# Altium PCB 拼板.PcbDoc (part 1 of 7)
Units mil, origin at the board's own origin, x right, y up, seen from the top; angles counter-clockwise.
Board outline 3630.03 x 5330.03 mil, 2 copper layers (Top Layer, Bottom Layer); 416 components, 35 nets, 1936 pads, 800 vias.
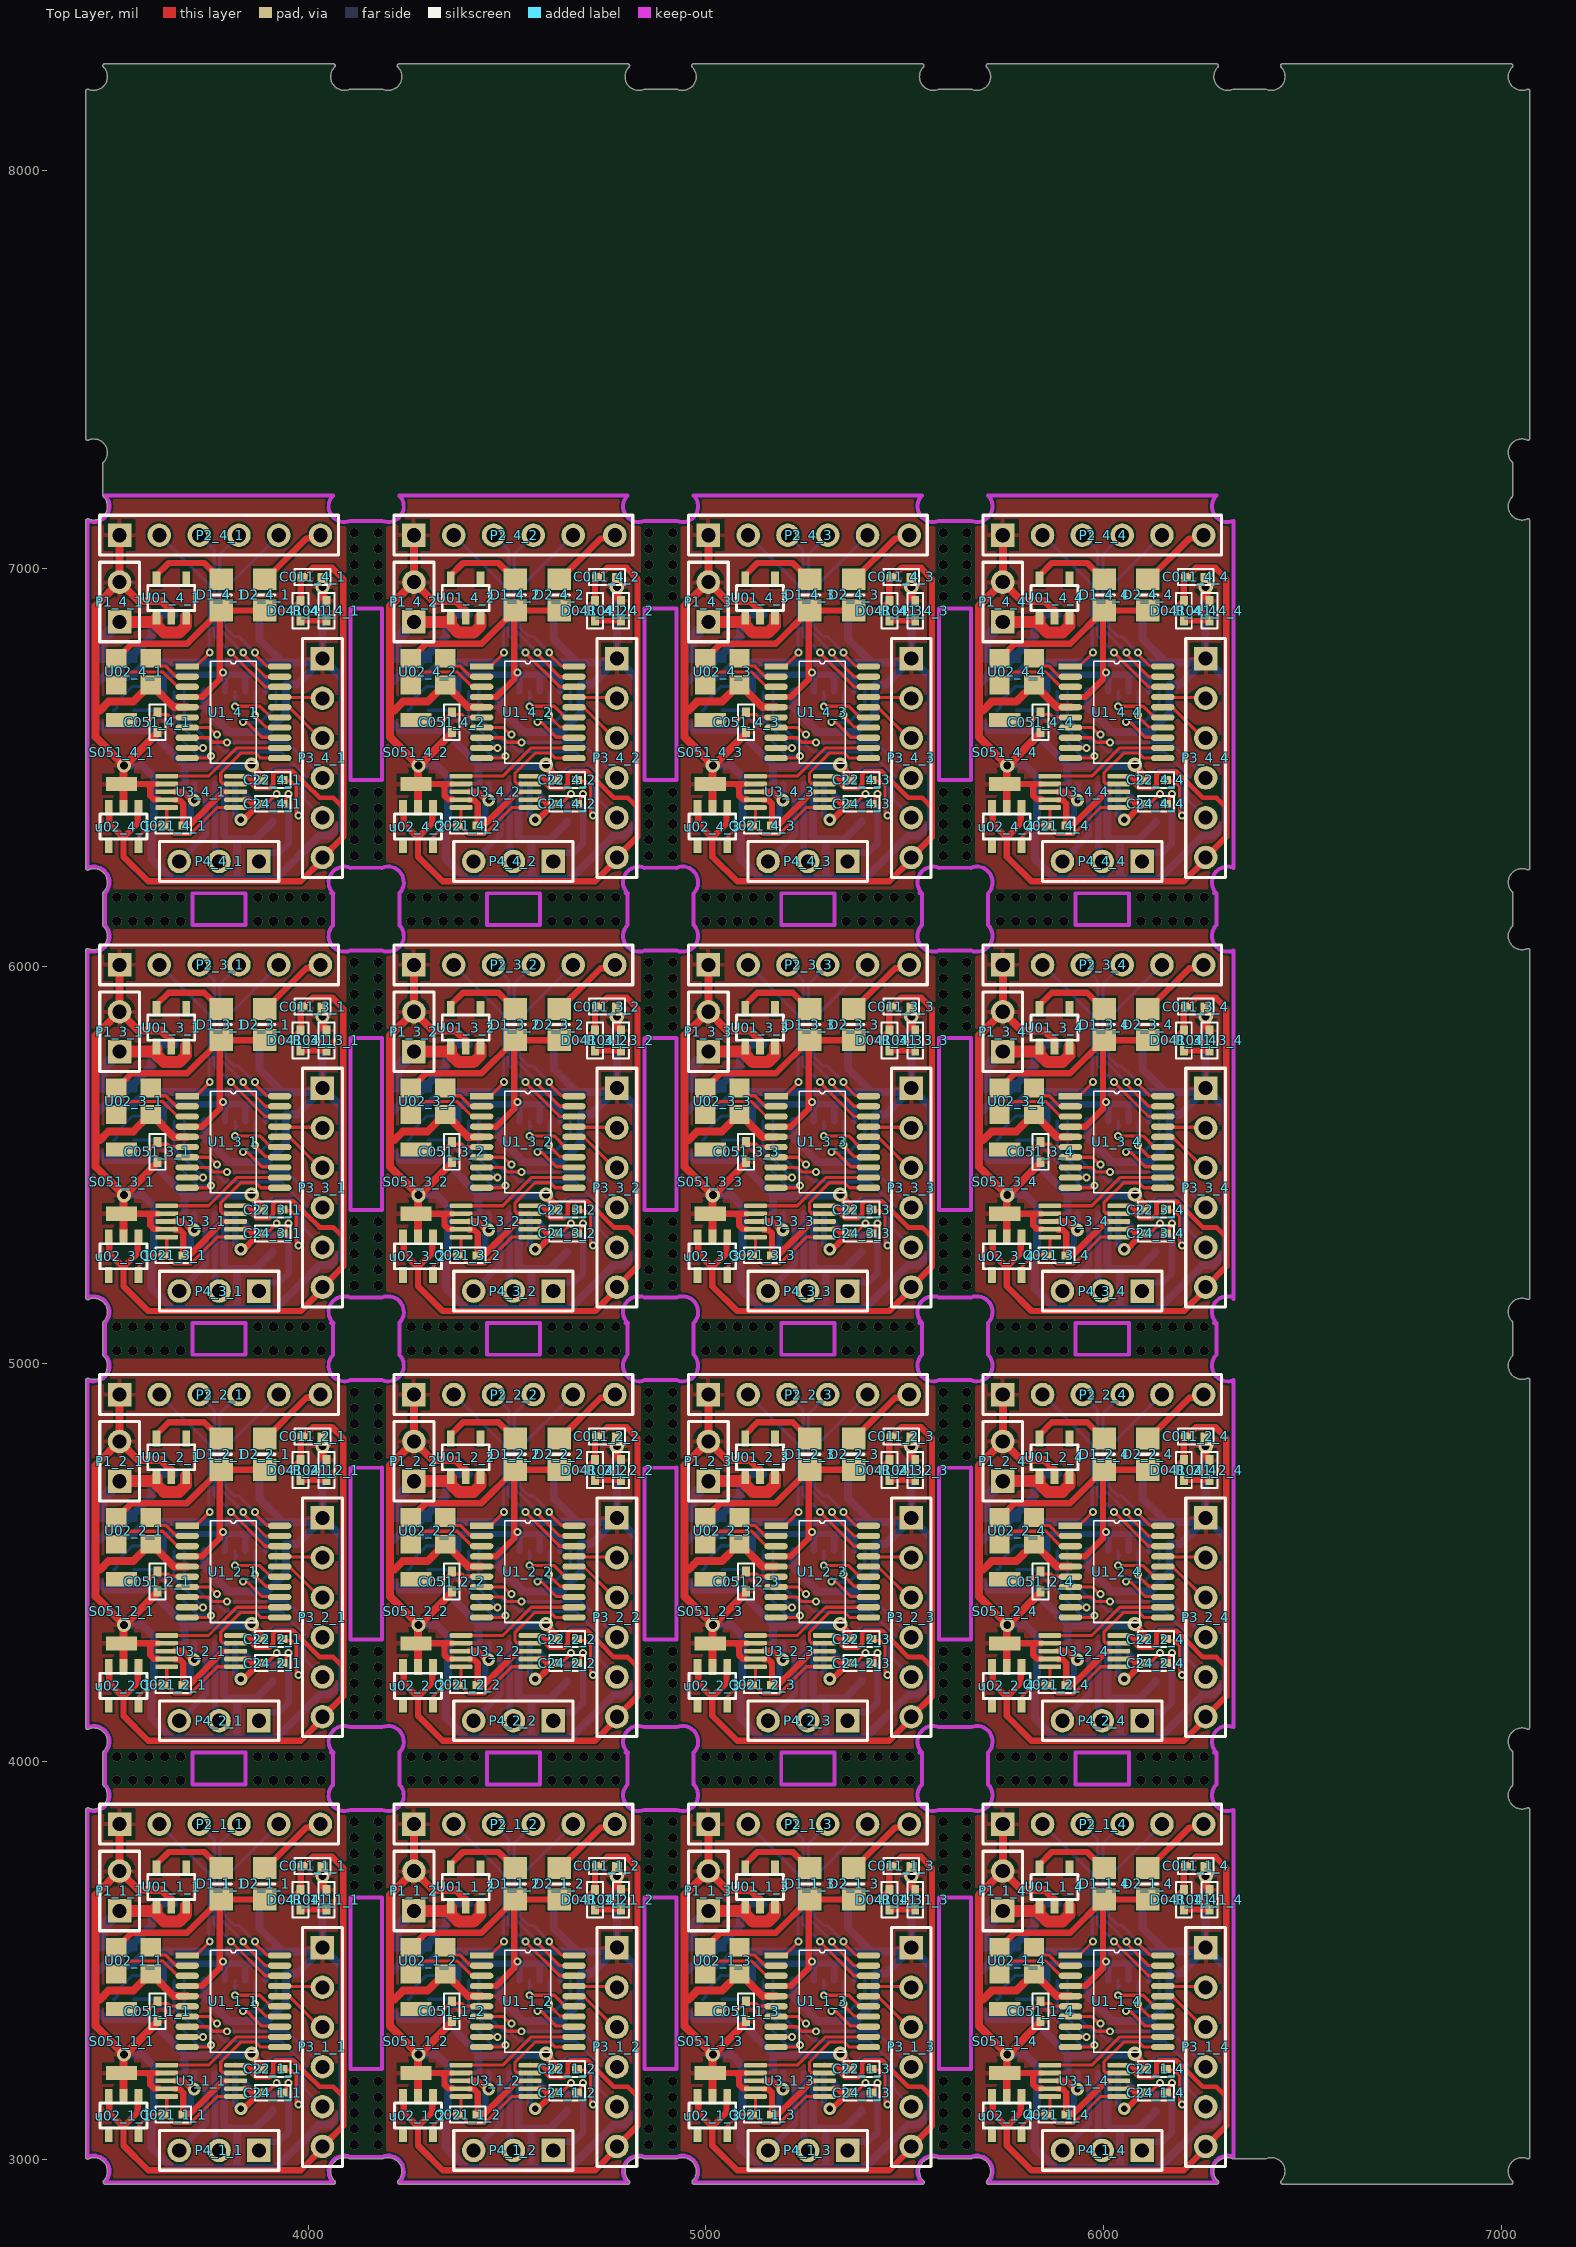
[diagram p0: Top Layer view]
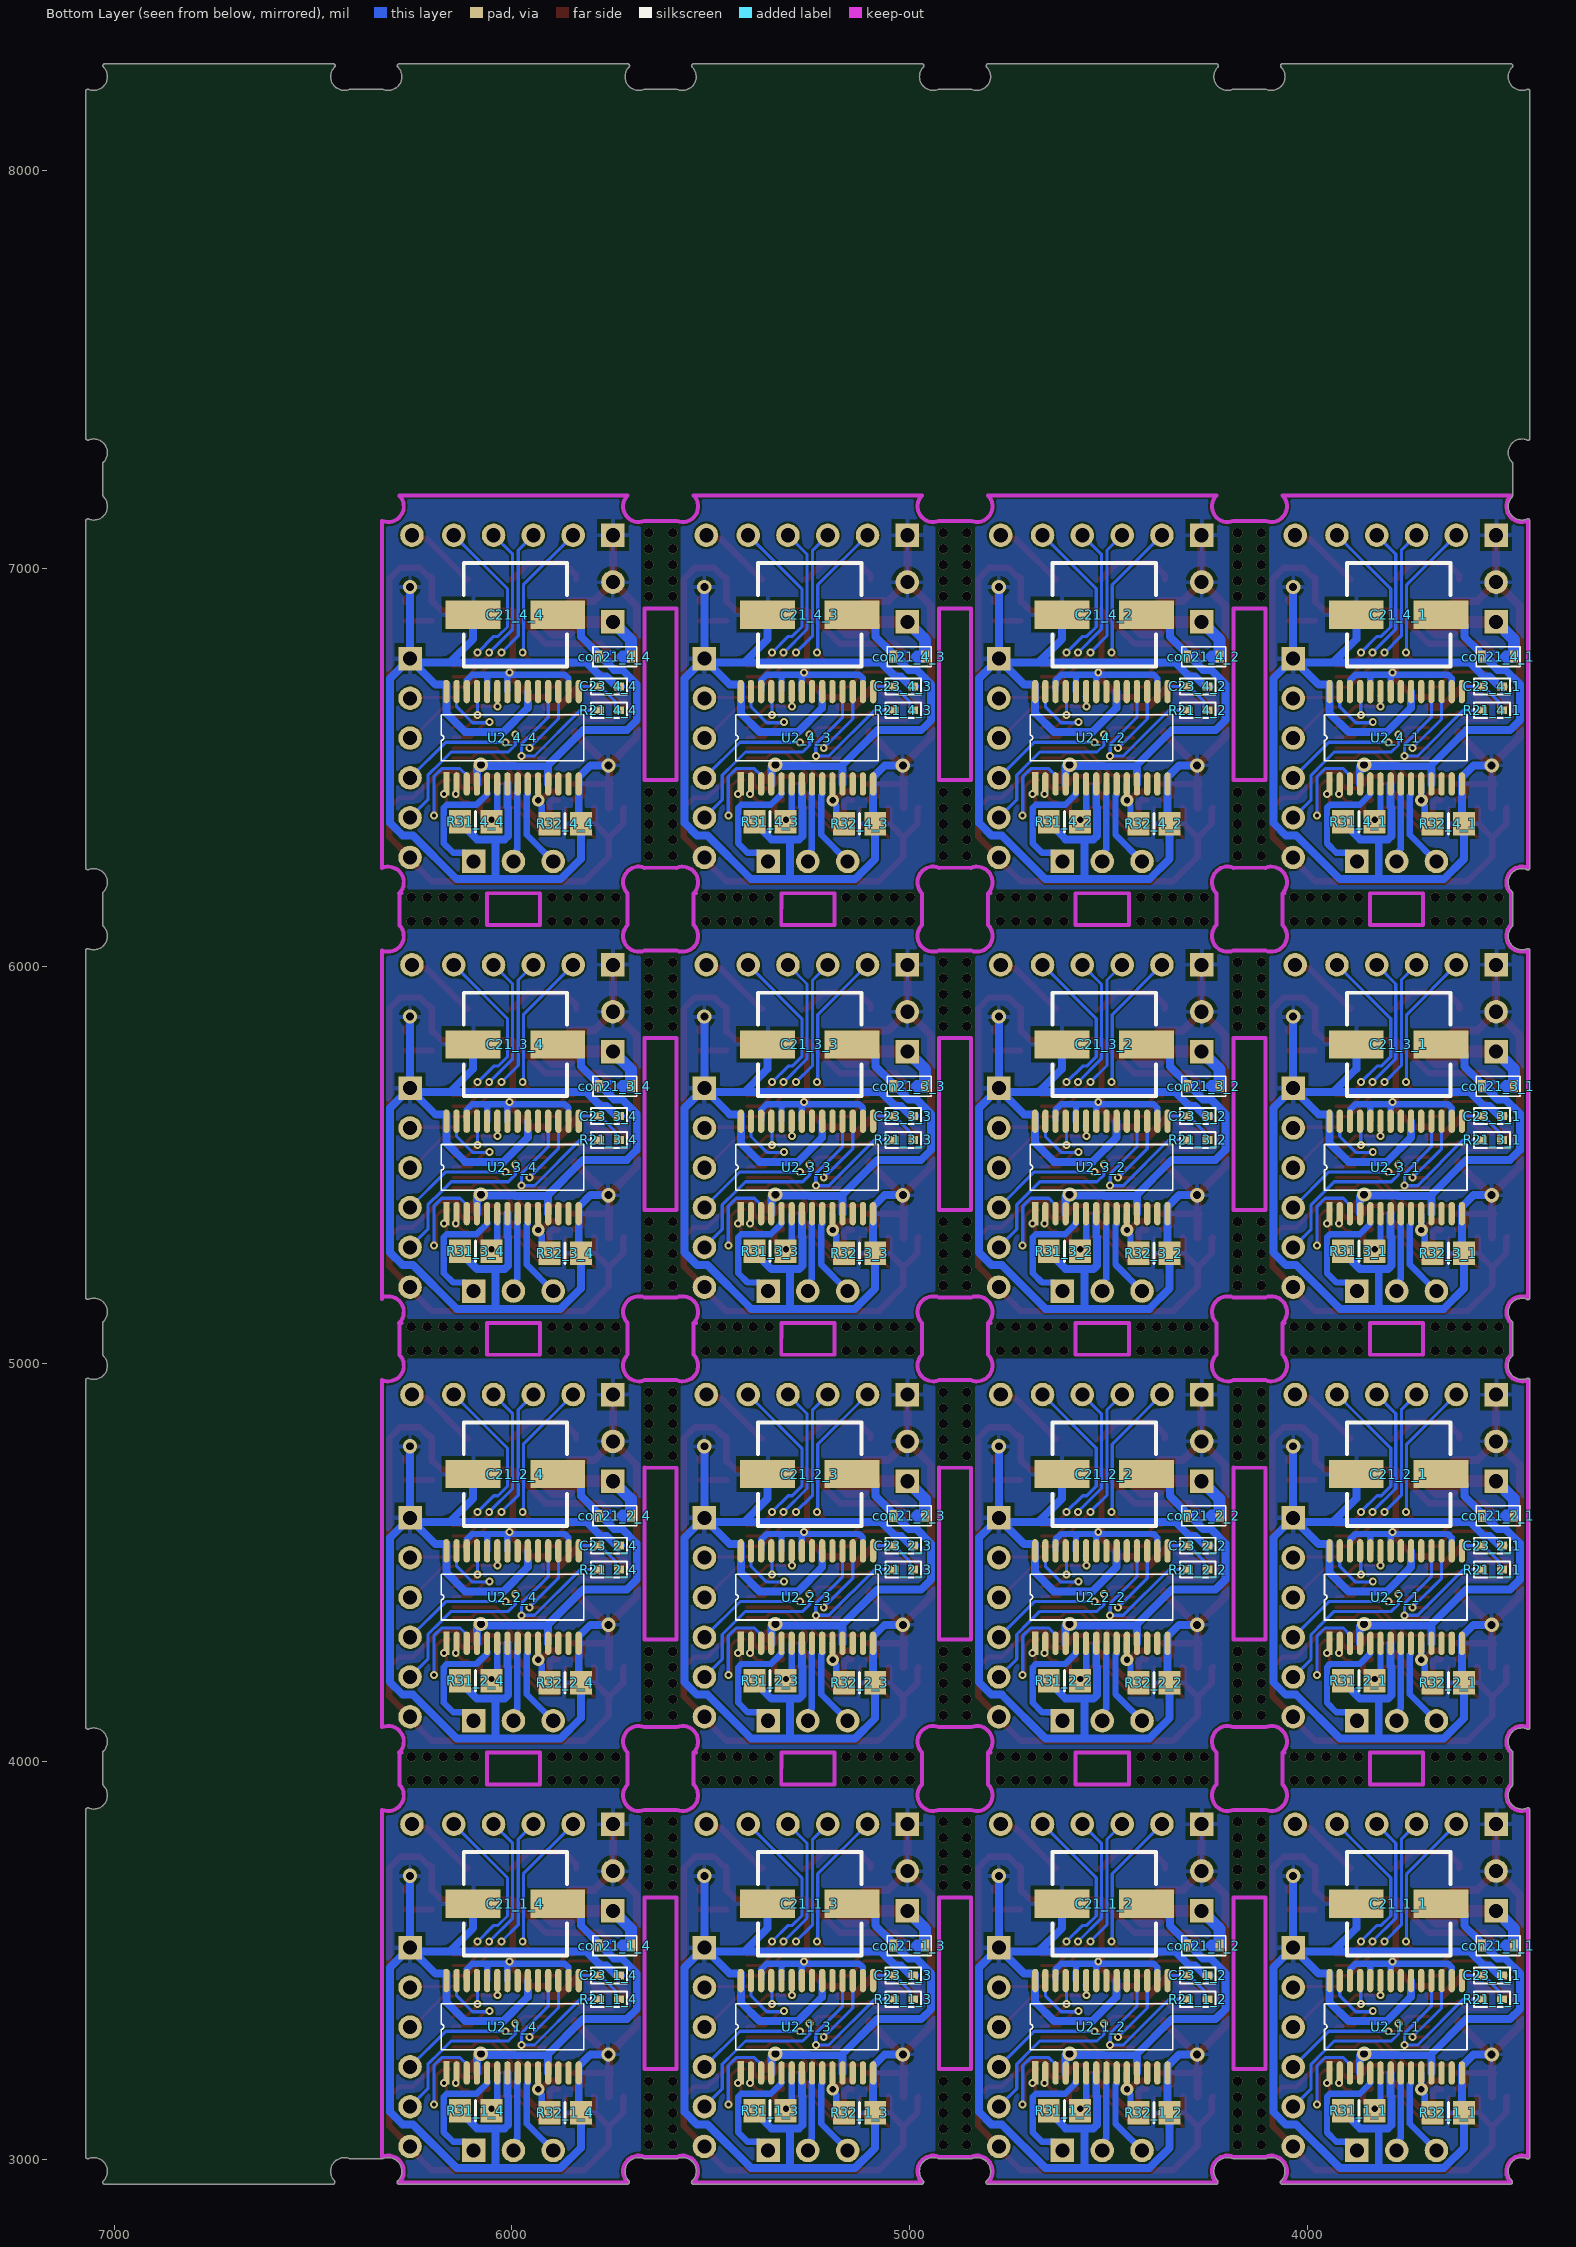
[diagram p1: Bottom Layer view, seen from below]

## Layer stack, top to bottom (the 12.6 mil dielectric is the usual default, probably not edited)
Top Solder: solder mask 0.4, Solder Resist, Dk 3.5
Top Layer: signal copper 1.4
Dielectric 1: dielectric 12.6, FR-4, Dk 4.8
Bottom Layer: signal copper 1.4
Bottom Solder: solder mask 0.4, Solder Resist, Dk 3.5

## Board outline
3441.05,3006.39 3441.05,3879.08 cw(c3446.07,3879.08) 3447.98,3883.71 ccw(c3461.11,3915.46) 3495.46,3915.46 ccw(c3461.11,3915.46) 3485.66,3939.49 ccw(c3461.11,3915.46) 3485.64,3939.51 cw(c3489.22,3943.02) 3484.21,3943.04 3484.21,3943.01 ccw(c3489.22,3943.02) 3485.66,3939.49 3484.21,3943.04 3484.05,4023.01 cw(c3489.07,4023.02) 3486.27,4027.19 cw(c3490.1,4023.95) 3486.41,4027.34 ccw(c3461.11,4050.58) 3495.46,4050.58 ccw(c3461.11,4050.58) 3449.77,4083.01 cw(c3446.07,4086.39) 3441.05,4086.39 3441.05,4959.08 cw(c3446.07,4959.08) 3447.98,4963.71 ccw(c3461.11,4995.46) 3495.46,4995.46 ccw(c3461.11,4995.46) 3485.66,5019.49 ccw(c3461.11,4995.46) 3485.64,5019.51 cw(c3489.22,5023.02) 3484.21,5023.04 3484.05,5103.01 cw(c3489.07,5103.02) 3486.27,5107.19 cw(c3490.1,5103.95) 3486.41,5107.34 ccw(c3461.11,5130.58) 3495.46,5130.58 ccw(c3461.11,5130.58) 3449.77,5163.01 cw(c3446.07,5166.39) 3441.05,5166.39 3441.05,6039.08 cw(c3446.07,6039.08) 3447.98,6043.71 ccw(c3461.11,6075.46) 3495.46,6075.46 ccw(c3461.11,6075.46) 3485.66,6099.49 ccw(c3461.11,6075.46) 3485.64,6099.51 cw(c3489.22,6103.02) 3484.21,6103.04 3484.21,6103.01 ccw(c3489.22,6103.02) 3485.66,6099.49 3484.21,6103.04 3484.05,6183.01 cw(c3489.07,6183.02) 3486.27,6187.19 cw(c3490.1,6183.95) 3486.41,6187.34 ccw(c3461.11,6210.58) 3495.46,6210.58 ccw(c3461.11,6210.58) 3449.77,6243.01 cw(c3446.07,6246.39) 3441.05,6246.39 3441.05,7119.08 cw(c3446.07,7119.08) 3447.98,7123.71 ccw(c3461.11,7155.46) 3495.46,7155.46 ccw(c3461.11,7155.46) 3485.66,7179.49 ccw(c3461.11,7155.46) 3485.64,7179.51 cw(c3489.22,7183.02) 3484.21,7183.04 3484.21,7183.01 ccw(c3489.22,7183.02) 3485.66,7179.49 3484.21,7183.04 3484.05,7263.01 cw(c3489.07,7263.02) 3486.27,7267.19 cw(c3490.1,7263.95) 3486.41,7267.34 ccw(c3461.11,7290.58) 3495.46,7290.58 ccw(c3461.11,7290.58) 3449.77,7323.01 cw(c3446.07,7326.39) 3441.05,7326.39 3441.05,8199.08 cw(c3446.07,8199.08) 3447.98,8203.71 ccw(c3461.11,8235.46) 3495.46,8235.46 ccw(c3461.11,8235.46) 3485.67,8259.48 ccw(c3461.11,8235.46) 3485.64,8259.51 3485.67,8259.48 cw(c3489.22,8263.02) 3484.21,8263.02 cw(c3489.22,8263.02) 3489.25,8268.04 4062.91,8268.04 cw(c4062.91,8263.02) 4067.93,8263.02 cw(c4062.91,8263.02) 4066.47,8259.49 cw(c4091.03,8235.46) 4066.49,8259.51 4066.47,8259.49 ccw(c4091.03,8235.46) 4104.15,8203.71 cw(c4106.07,8199.08) 4106.07,8204.09 4186.07,8204.09 cw(c4186.07,8199.08) 4187.98,8203.71 ccw(c4201.11,8235.46) 4235.46,8235.46 ccw(c4201.11,8235.46) 4225.67,8259.48 ccw(c4201.11,8235.46) 4225.64,8259.51 4225.67,8259.48 cw(c4229.22,8263.02) 4224.21,8263.02 cw(c4229.22,8263.02) 4229.25,8268.04 4802.91,8268.04 cw(c4802.91,8263.02) 4807.93,8263.02 cw(c4802.91,8263.02) 4806.47,8259.49 cw(c4831.03,8235.46) 4806.49,8259.51 4806.47,8259.49 ccw(c4831.03,8235.46) 4844.15,8203.71 cw(c4846.07,8199.08) 4846.07,8204.09 4926.07,8204.09 cw(c4926.07,8199.08) 4927.98,8203.71 ccw(c4941.11,8235.46) 4975.46,8235.46 ccw(c4941.11,8235.46) 4965.67,8259.48 ccw(c4941.11,8235.46) 4965.64,8259.51 4965.67,8259.48 cw(c4969.22,8263.02) 4964.21,8263.02 cw(c4969.22,8263.02) 4969.25,8268.04 5542.91,8268.04 cw(c5542.91,8263.02) 5547.93,8263.02 cw(c5542.91,8263.02) 5546.47,8259.49 cw(c5571.03,8235.46) 5546.49,8259.51 5546.47,8259.49 ccw(c5571.03,8235.46) 5584.15,8203.71 cw(c5586.07,8199.08) 5586.07,8204.09 5666.07,8204.09 cw(c5666.07,8199.08) 5667.98,8203.71 ccw(c5681.11,8235.46) 5715.46,8235.46 ccw(c5681.11,8235.46) 5705.67,8259.48 ccw(c5681.11,8235.46) 5705.64,8259.51 5705.67,8259.48 cw(c5709.22,8263.02) 5704.21,8263.02 cw(c5709.22,8263.02) 5709.25,8268.04 6282.91,8268.04 cw(c6282.91,8263.02) 6287.93,8263.02 cw(c6282.91,8263.02) 6286.47,8259.49 cw(c6311.03,8235.46) 6286.49,8259.51 6286.47,8259.49 ccw(c6311.03,8235.46) 6324.15,8203.71 cw(c6326.07,8199.08) 6326.07,8204.09 6406.07,8204.09 cw(c6406.07,8199.08) 6407.98,8203.71 ccw(c6421.11,8235.46) 6455.46,8235.46 ccw(c6421.11,8235.46) 6445.67,8259.48 ccw(c6421.11,8235.46) 6445.64,8259.51 6445.67,8259.48 cw(c6449.22,8263.02) 6444.21,8263.02 cw(c6449.22,8263.02) 6449.25,8268.04 7022.91,8268.04 cw(c7022.91,8263.02) 7027.93,8263.02 cw(c7022.91,8263.02) 7026.47,8259.49 cw(c7051.03,8235.46) 7026.49,8259.51 7026.47,8259.49 ccw(c7051.03,8235.46) 7064.15,8203.71 cw(c7066.07,8199.08) 7071.08,8199.08 cw(c7066.07,8199.08) 7071.08,8199.08 7071.08,7326.97 cw(c7066.07,7326.97) 7064.15,7322.33 ccw(c7051.03,7290.58) 7025.44,7267.65 cw(c7023.51,7263.02) 7028.53,7263.02 cw(c7023.51,7263.02) 7027.93,7260.64 7027.93,7183.02 cw(c7022.91,7183.02) 7026.47,7179.49 cw(c7051.03,7155.46) 7026.49,7179.51 7026.47,7179.49 ccw(c7051.03,7155.46) 7064.15,7123.71 cw(c7066.07,7119.08) 7071.08,7119.08 cw(c7066.07,7119.08) 7071.08,7119.08 7071.08,6246.97 cw(c7066.07,6246.97) 7064.15,6242.33 ccw(c7051.03,6210.58) 7025.44,6187.65 cw(c7023.51,6183.02) 7028.53,6183.02 cw(c7023.51,6183.02) 7027.93,6180.64 7027.93,6103.02 cw(c7022.91,6103.02) 7026.47,6099.49 ccw(c7051.03,6075.46) 7064.15,6043.71 cw(c7066.07,6039.08) 7071.08,6039.08 cw(c7066.07,6039.08) 7071.08,6039.08 7071.08,5166.97 cw(c7066.07,5166.97) 7064.15,5162.33 ccw(c7051.03,5130.58) 7025.44,5107.65 cw(c7023.51,5103.02) 7028.53,5103.02 cw(c7023.51,5103.02) 7027.93,5100.64 7027.93,5023.02 cw(c7022.91,5023.02) 7026.47,5019.49 cw(c7051.03,4995.46) 7026.49,5019.51 7026.47,5019.49 ccw(c7051.03,4995.46) 7064.15,4963.71 cw(c7066.07,4959.08) 7071.08,4959.08 cw(c7066.07,4959.08) 7071.08,4959.08 7071.08,4086.97 cw(c7066.07,4086.97) 7064.15,4082.33 ccw(c7051.03,4050.58) 7025.44,4027.65 cw(c7023.51,4023.02) 7028.53,4023.02 cw(c7023.51,4023.02) 7027.93,4020.64 7027.93,3943.02 cw(c7022.91,3943.02) 7026.47,3939.49 cw(c7051.03,3915.46) 7026.49,3939.51 7026.47,3939.49 ccw(c7051.03,3915.46) 7064.15,3883.71 cw(c7066.07,3879.08) 7071.08,3879.08 cw(c7066.07,3879.08) 7071.08,3879.08 7071.08,3006.97 cw(c7066.07,3006.97) 7064.15,3002.33 ccw(c7051.03,2970.58) 7025.44,2947.65 cw(c7023.51,2943.02) 7028.53,2943.02 cw(c7023.51,2943.02) 7023.51,2938.01 7017.29,2938.01 cw(c7017.29,2943.02) 7017.29,2938.01 ccw(c7017.29,2943.02) 7017.32,2938.01 7017.29,2938.01 6450.1,2938.01 cw(c6450.1,2943.02) 6445.11,2943.49 cw(c6450.1,2943.95) 6446.41,2947.34 ccw(c6421.11,2970.58) 6455.46,2970.58 ccw(c6421.11,2970.58) 6407.98,3002.33 cw(c6406.07,3006.97) 6404.83,3002.1 6326.08,3001.95 cw(c6326.07,3006.97) 6324.15,3002.33 ccw(c6311.03,2970.58) 6285.44,2947.65 cw(c6283.51,2943.02) 6288.53,2943.02 cw(c6283.51,2943.02) 6283.51,2938.01 6277.29,2938.01 cw(c6277.29,2943.02) 6277.29,2938.01 ccw(c6277.29,2943.02) 6277.32,2938.01 6277.29,2938.01 5710.1,2938.01 cw(c5710.1,2943.02) 5705.11,2943.49 cw(c5710.1,2943.95) 5706.41,2947.34 ccw(c5681.11,2970.58) 5715.46,2970.58 ccw(c5681.11,2970.58) 5667.98,3002.33 cw(c5666.07,3006.97) 5664.83,3002.1 5586.08,3001.95 cw(c5586.07,3006.97) 5584.15,3002.33 ccw(c5571.03,2970.58) 5545.44,2947.65 cw(c5543.51,2943.02) 5548.53,2943.02 cw(c5543.51,2943.02) 5543.51,2938.01 5537.29,2938.01 cw(c5537.29,2943.02) 5537.29,2938.01 ccw(c5537.29,2943.02) 5537.32,2938.01 5537.29,2938.01 4970.1,2938.01 cw(c4970.1,2943.02) 4965.11,2943.49 cw(c4970.1,2943.95) 4966.41,2947.34 ccw(c4941.11,2970.58) 4975.46,2970.58 ccw(c4941.11,2970.58) 4927.98,3002.33 cw(c4926.07,3006.97) 4924.83,3002.1 4846.08,3001.95 cw(c4846.07,3006.97) 4844.15,3002.33 ccw(c4831.03,2970.58) 4805.44,2947.65 cw(c4803.51,2943.02) 4808.53,2943.02 cw(c4803.51,2943.02) 4803.51,2938.01 4797.29,2938.01 cw(c4797.29,2943.02) 4797.29,2938.01 ccw(c4797.29,2943.02) 4797.32,2938.01 4797.29,2938.01 4230.1,2938.01 cw(c4230.1,2943.02) 4225.11,2943.49 cw(c4230.1,2943.95) 4226.41,2947.34 ccw(c4201.11,2970.58) 4235.46,2970.58 ccw(c4201.11,2970.58) 4187.98,3002.33 cw(c4186.07,3006.97) 4184.83,3002.1 4106.08,3001.95 cw(c4106.07,3006.97) 4104.15,3002.33 ccw(c4091.03,2970.58) 4065.44,2947.65 cw(c4063.51,2943.02) 4068.53,2943.02 cw(c4063.51,2943.02) 4063.51,2938.01 4057.29,2938.01 cw(c4057.29,2943.02) 4057.29,2938.01 ccw(c4057.29,2943.02) 4057.32,2938.01 4057.29,2938.01 3490.1,2938.01 cw(c3490.1,2943.02) 3485.11,2943.49 cw(c3490.1,2943.95) 3486.41,2947.34 ccw(c3461.11,2970.58) 3495.46,2970.58 ccw(c3461.11,2970.58) 3449.77,3003.01 cw(c3446.07,3006.39)

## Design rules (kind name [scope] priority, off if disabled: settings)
Clearance chip_pin [HasFootprint('QFN24')] p1: gap=5 ignorepadtopadclearanceinfootprint=FALSE
Clearance [All] p2: gap=5 ignorepadtopadclearanceinfootprint=FALSE
HoleSize [All] p1: absolutevalues=TRUE maxlimit=20 minlimit=10 maxpercent=80.000 minpercent=20.000
PolygonConnect [All] p1: connectstyle=Relief reliefconductorwidth=10 reliefentries=4 polygonreliefangle="90 Angle" airgapwidth=10
RoutingVias [All] p1: holewidth=10 width=20 viastyle="Through Hole" minholewidth=10 minwidth=20 maxholewidth=20 maxwidth=40
SolderMaskExpansion [All] p1: expansion=4 istentingtop=FALSE
Width VCC [InNet('VCC')or InNet('VCC_in')] p1: maxlimit=30 minlimit=20 preferedwidth=20
Width GND [InNet('GND')] p2: maxlimit=30 minlimit=8 preferedwidth=20
Width Power [(InNet('OUTPUT1') OR InNet('OUTPUT2') OR InNet('OUTPUT3') OR InNet('3V3')  OR InNet('PGND1') OR InNet('PGND3')  OR InNet('NetC011_1') OR InNet('NetD1_1')  OR InNet('NetD2_1'))] p3: maxlimit=20 minlimit=10 preferedwidth=15
Width signal [All] p4: maxlimit=15 minlimit=8 preferedwidth=8
29 further rules are at their usual default settings.

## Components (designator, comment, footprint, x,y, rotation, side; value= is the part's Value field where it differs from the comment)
C011_1_1 "Cap" 0402R 4011.07,3738.02 r0 top value=10uF (schematic designator C011)
C011_1_2 "Cap" 0402R 4751.07,3738.02 r0 top value=10uF (schematic designator C011)
C011_1_3 "Cap" 0402R 5491.07,3738.02 r0 top value=10uF (schematic designator C011)
C011_1_4 "Cap" 0402R 6231.07,3738.02 r0 top value=10uF (schematic designator C011)
C011_2_1 "Cap" 0402R 4011.07,4818.02 r0 top value=10uF (schematic designator C011)
C011_2_2 "Cap" 0402R 4751.07,4818.02 r0 top value=10uF (schematic designator C011)
C011_2_3 "Cap" 0402R 5491.07,4818.02 r0 top value=10uF (schematic designator C011)
C011_2_4 "Cap" 0402R 6231.07,4818.02 r0 top value=10uF (schematic designator C011)
C011_3_1 "Cap" 0402R 4011.07,5898.02 r0 top value=10uF (schematic designator C011)
C011_3_2 "Cap" 0402R 4751.07,5898.02 r0 top value=10uF (schematic designator C011)
C011_3_3 "Cap" 0402R 5491.07,5898.02 r0 top value=10uF (schematic designator C011)
C011_3_4 "Cap" 0402R 6231.07,5898.02 r0 top value=10uF (schematic designator C011)
C011_4_1 "Cap" 0402R 4011.07,6978.02 r0 top value=10uF (schematic designator C011)
C011_4_2 "Cap" 0402R 4751.07,6978.02 r0 top value=10uF (schematic designator C011)
C011_4_3 "Cap" 0402R 5491.07,6978.02 r0 top value=10uF (schematic designator C011)
C011_4_4 "Cap" 0402R 6231.07,6978.02 r0 top value=10uF (schematic designator C011)
C021_1_1 "Cap" 0402R 3661.07,3113.02 r0 top value=1uF (schematic designator C021)
C21_1_1 "Cap" XT_100UF_25V 3771.07,3643.02 r0 bottom locked value=100uF/25V (schematic designator C21)
C021_1_2 "Cap" 0402R 4401.07,3113.02 r0 top value=1uF (schematic designator C021)
C21_1_2 "Cap" XT_100UF_25V 4511.07,3643.02 r0 bottom locked value=100uF/25V (schematic designator C21)
C021_1_3 "Cap" 0402R 5141.07,3113.02 r0 top value=1uF (schematic designator C021)
C21_1_3 "Cap" XT_100UF_25V 5251.07,3643.02 r0 bottom locked value=100uF/25V (schematic designator C21)
C021_1_4 "Cap" 0402R 5881.07,3113.02 r0 top value=1uF (schematic designator C021)
C21_1_4 "Cap" XT_100UF_25V 5991.07,3643.02 r0 bottom locked value=100uF/25V (schematic designator C21)
C021_2_1 "Cap" 0402R 3661.07,4193.02 r0 top value=1uF (schematic designator C021)
C21_2_1 "Cap" XT_100UF_25V 3771.07,4723.02 r0 bottom locked value=100uF/25V (schematic designator C21)
C021_2_2 "Cap" 0402R 4401.07,4193.02 r0 top value=1uF (schematic designator C021)
C21_2_2 "Cap" XT_100UF_25V 4511.07,4723.02 r0 bottom locked value=100uF/25V (schematic designator C21)
C021_2_3 "Cap" 0402R 5141.07,4193.02 r0 top value=1uF (schematic designator C021)
C21_2_3 "Cap" XT_100UF_25V 5251.07,4723.02 r0 bottom locked value=100uF/25V (schematic designator C21)
C021_2_4 "Cap" 0402R 5881.07,4193.02 r0 top value=1uF (schematic designator C021)
C21_2_4 "Cap" XT_100UF_25V 5991.07,4723.02 r0 bottom locked value=100uF/25V (schematic designator C21)
C021_3_1 "Cap" 0402R 3661.07,5273.02 r0 top value=1uF (schematic designator C021)
C21_3_1 "Cap" XT_100UF_25V 3771.07,5803.02 r0 bottom locked value=100uF/25V (schematic designator C21)
C021_3_2 "Cap" 0402R 4401.07,5273.02 r0 top value=1uF (schematic designator C021)
C21_3_2 "Cap" XT_100UF_25V 4511.07,5803.02 r0 bottom locked value=100uF/25V (schematic designator C21)
C021_3_3 "Cap" 0402R 5141.07,5273.02 r0 top value=1uF (schematic designator C021)
C21_3_3 "Cap" XT_100UF_25V 5251.07,5803.02 r0 bottom locked value=100uF/25V (schematic designator C21)
C021_3_4 "Cap" 0402R 5881.07,5273.02 r0 top value=1uF (schematic designator C021)
C21_3_4 "Cap" XT_100UF_25V 5991.07,5803.02 r0 bottom locked value=100uF/25V (schematic designator C21)
C021_4_1 "Cap" 0402R 3661.07,6353.02 r0 top value=1uF (schematic designator C021)
C21_4_1 "Cap" XT_100UF_25V 3771.07,6883.02 r0 bottom locked value=100uF/25V (schematic designator C21)
C021_4_2 "Cap" 0402R 4401.07,6353.02 r0 top value=1uF (schematic designator C021)
C21_4_2 "Cap" XT_100UF_25V 4511.07,6883.02 r0 bottom locked value=100uF/25V (schematic designator C21)
C021_4_3 "Cap" 0402R 5141.07,6353.02 r0 top value=1uF (schematic designator C021)
C21_4_3 "Cap" XT_100UF_25V 5251.07,6883.02 r0 bottom locked value=100uF/25V (schematic designator C21)
C021_4_4 "Cap" 0402R 5881.07,6353.02 r0 top value=1uF (schematic designator C021)
C21_4_4 "Cap" XT_100UF_25V 5991.07,6883.02 r0 bottom locked value=100uF/25V (schematic designator C21)
C22_1_1 "Cap" 0402R 3911.07,3228.02 r0 top value=0.1uF (schematic designator C22)
C22_1_2 "Cap" 0402R 4651.07,3228.02 r0 top value=0.1uF (schematic designator C22)
C22_1_3 "Cap" 0402R 5391.07,3228.02 r0 top value=0.1uF (schematic designator C22)
C22_1_4 "Cap" 0402R 6131.07,3228.02 r0 top value=0.1uF (schematic designator C22)
C22_2_1 "Cap" 0402R 3911.07,4308.02 r0 top value=0.1uF (schematic designator C22)
C22_2_2 "Cap" 0402R 4651.07,4308.02 r0 top value=0.1uF (schematic designator C22)
C22_2_3 "Cap" 0402R 5391.07,4308.02 r0 top value=0.1uF (schematic designator C22)
C22_2_4 "Cap" 0402R 6131.07,4308.02 r0 top value=0.1uF (schematic designator C22)
C22_3_1 "Cap" 0402R 3911.07,5388.02 r0 top value=0.1uF (schematic designator C22)
C22_3_2 "Cap" 0402R 4651.07,5388.02 r0 top value=0.1uF (schematic designator C22)
C22_3_3 "Cap" 0402R 5391.07,5388.02 r0 top value=0.1uF (schematic designator C22)
C22_3_4 "Cap" 0402R 6131.07,5388.02 r0 top value=0.1uF (schematic designator C22)
C22_4_1 "Cap" 0402R 3911.07,6468.02 r0 top value=0.1uF (schematic designator C22)
C22_4_2 "Cap" 0402R 4651.07,6468.02 r0 top value=0.1uF (schematic designator C22)
C22_4_3 "Cap" 0402R 5391.07,6468.02 r0 top value=0.1uF (schematic designator C22)
C22_4_4 "Cap" 0402R 6131.07,6468.02 r0 top value=0.1uF (schematic designator C22)
C23_1_1 "Cap" 0402R 3536.07,3463.02 r180 bottom value=0.47uF (schematic designator C23)
C23_1_2 "Cap" 0402R 4276.07,3463.02 r180 bottom value=0.47uF (schematic designator C23)
C23_1_3 "Cap" 0402R 5016.07,3463.02 r180 bottom value=0.47uF (schematic designator C23)
C23_1_4 "Cap" 0402R 5756.07,3463.02 r180 bottom value=0.47uF (schematic designator C23)
C23_2_1 "Cap" 0402R 3536.07,4543.02 r180 bottom value=0.47uF (schematic designator C23)
C23_2_2 "Cap" 0402R 4276.07,4543.02 r180 bottom value=0.47uF (schematic designator C23)
C23_2_3 "Cap" 0402R 5016.07,4543.02 r180 bottom value=0.47uF (schematic designator C23)
C23_2_4 "Cap" 0402R 5756.07,4543.02 r180 bottom value=0.47uF (schematic designator C23)
C23_3_1 "Cap" 0402R 3536.07,5623.02 r180 bottom value=0.47uF (schematic designator C23)
C23_3_2 "Cap" 0402R 4276.07,5623.02 r180 bottom value=0.47uF (schematic designator C23)
C23_3_3 "Cap" 0402R 5016.07,5623.02 r180 bottom value=0.47uF (schematic designator C23)
C23_3_4 "Cap" 0402R 5756.07,5623.02 r180 bottom value=0.47uF (schematic designator C23)
C23_4_1 "Cap" 0402R 3536.07,6703.02 r180 bottom value=0.47uF (schematic designator C23)
C23_4_2 "Cap" 0402R 4276.07,6703.02 r180 bottom value=0.47uF (schematic designator C23)
C23_4_3 "Cap" 0402R 5016.07,6703.02 r180 bottom value=0.47uF (schematic designator C23)
C23_4_4 "Cap" 0402R 5756.07,6703.02 r180 bottom value=0.47uF (schematic designator C23)
C24_1_1 "Cap" 0402R 3911.07,3168.02 r180 top value=0.01uF (schematic designator C24)
C24_1_2 "Cap" 0402R 4651.07,3168.02 r180 top value=0.01uF (schematic designator C24)
C24_1_3 "Cap" 0402R 5391.07,3168.02 r180 top value=0.01uF (schematic designator C24)
C24_1_4 "Cap" 0402R 6131.07,3168.02 r180 top value=0.01uF (schematic designator C24)
C24_2_1 "Cap" 0402R 3911.07,4248.02 r180 top value=0.01uF (schematic designator C24)
C24_2_2 "Cap" 0402R 4651.07,4248.02 r180 top value=0.01uF (schematic designator C24)
C24_2_3 "Cap" 0402R 5391.07,4248.02 r180 top value=0.01uF (schematic designator C24)
C24_2_4 "Cap" 0402R 6131.07,4248.02 r180 top value=0.01uF (schematic designator C24)
C24_3_1 "Cap" 0402R 3911.07,5328.02 r180 top value=0.01uF (schematic designator C24)
C24_3_2 "Cap" 0402R 4651.07,5328.02 r180 top value=0.01uF (schematic designator C24)
C24_3_3 "Cap" 0402R 5391.07,5328.02 r180 top value=0.01uF (schematic designator C24)
C24_3_4 "Cap" 0402R 6131.07,5328.02 r180 top value=0.01uF (schematic designator C24)
C24_4_1 "Cap" 0402R 3911.07,6408.02 r180 top value=0.01uF (schematic designator C24)
C24_4_2 "Cap" 0402R 4651.07,6408.02 r180 top value=0.01uF (schematic designator C24)
C24_4_3 "Cap" 0402R 5391.07,6408.02 r180 top value=0.01uF (schematic designator C24)
C24_4_4 "Cap" 0402R 6131.07,6408.02 r180 top value=0.01uF (schematic designator C24)
C051_1_1 "Cap" 0402R 3621.07,3373.02 r270 top value=0.1μF (schematic designator C051)
C051_1_2 "Cap" 0402R 4361.07,3373.02 r270 top value=0.1μF (schematic designator C051)
C051_1_3 "Cap" 0402R 5101.07,3373.02 r270 top value=0.1μF (schematic designator C051)
C051_1_4 "Cap" 0402R 5841.07,3373.02 r270 top value=0.1μF (schematic designator C051)
C051_2_1 "Cap" 0402R 3621.07,4453.02 r270 top value=0.1μF (schematic designator C051)
C051_2_2 "Cap" 0402R 4361.07,4453.02 r270 top value=0.1μF (schematic designator C051)
C051_2_3 "Cap" 0402R 5101.07,4453.02 r270 top value=0.1μF (schematic designator C051)
C051_2_4 "Cap" 0402R 5841.07,4453.02 r270 top value=0.1μF (schematic designator C051)
C051_3_1 "Cap" 0402R 3621.07,5533.02 r270 top value=0.1μF (schematic designator C051)
C051_3_2 "Cap" 0402R 4361.07,5533.02 r270 top value=0.1μF (schematic designator C051)
C051_3_3 "Cap" 0402R 5101.07,5533.02 r270 top value=0.1μF (schematic designator C051)
C051_3_4 "Cap" 0402R 5841.07,5533.02 r270 top value=0.1μF (schematic designator C051)
C051_4_1 "Cap" 0402R 3621.07,6613.02 r270 top value=0.1μF (schematic designator C051)
C051_4_2 "Cap" 0402R 4361.07,6613.02 r270 top value=0.1μF (schematic designator C051)
C051_4_3 "Cap" 0402R 5101.07,6613.02 r270 top value=0.1μF (schematic designator C051)
C051_4_4 "Cap" 0402R 5841.07,6613.02 r270 top value=0.1μF (schematic designator C051)
con21_1_1 "connector" connector 3521.07,3538.02 r0 bottom (schematic designator con21)
con21_1_2 "connector" connector 4261.07,3538.02 r0 bottom (schematic designator con21)
con21_1_3 "connector" connector 5001.07,3538.02 r0 bottom (schematic designator con21)
con21_1_4 "connector" connector 5741.07,3538.02 r0 bottom (schematic designator con21)
con21_2_1 "connector" connector 3521.07,4618.02 r0 bottom (schematic designator con21)
con21_2_2 "connector" connector 4261.07,4618.02 r0 bottom (schematic designator con21)
con21_2_3 "connector" connector 5001.07,4618.02 r0 bottom (schematic designator con21)
con21_2_4 "connector" connector 5741.07,4618.02 r0 bottom (schematic designator con21)
con21_3_1 "connector" connector 3521.07,5698.02 r0 bottom (schematic designator con21)
con21_3_2 "connector" connector 4261.07,5698.02 r0 bottom (schematic designator con21)
con21_3_3 "connector" connector 5001.07,5698.02 r0 bottom (schematic designator con21)
con21_3_4 "connector" connector 5741.07,5698.02 r0 bottom (schematic designator con21)
con21_4_1 "connector" connector 3521.07,6778.02 r0 bottom (schematic designator con21)
con21_4_2 "connector" connector 4261.07,6778.02 r0 bottom (schematic designator con21)
con21_4_3 "connector" connector 5001.07,6778.02 r0 bottom (schematic designator con21)
con21_4_4 "connector" connector 5741.07,6778.02 r0 bottom (schematic designator con21)
D1_1_1 "Diode" 6-0805_M 3781.07,3693.02 r270 top (schematic designator D1)
D1_1_2 "Diode" 6-0805_M 4521.07,3693.02 r270 top (schematic designator D1)
D1_1_3 "Diode" 6-0805_M 5261.07,3693.02 r270 top (schematic designator D1)
D1_1_4 "Diode" 6-0805_M 6001.07,3693.02 r270 top (schematic designator D1)
D1_2_1 "Diode" 6-0805_M 3781.07,4773.02 r270 top (schematic designator D1)
D1_2_2 "Diode" 6-0805_M 4521.07,4773.02 r270 top (schematic designator D1)
D1_2_3 "Diode" 6-0805_M 5261.07,4773.02 r270 top (schematic designator D1)
D1_2_4 "Diode" 6-0805_M 6001.07,4773.02 r270 top (schematic designator D1)
D1_3_1 "Diode" 6-0805_M 3781.07,5853.02 r270 top (schematic designator D1)
D1_3_2 "Diode" 6-0805_M 4521.07,5853.02 r270 top (schematic designator D1)
D1_3_3 "Diode" 6-0805_M 5261.07,5853.02 r270 top (schematic designator D1)
D1_3_4 "Diode" 6-0805_M 6001.07,5853.02 r270 top (schematic designator D1)
D1_4_1 "Diode" 6-0805_M 3781.07,6933.02 r270 top (schematic designator D1)
D1_4_2 "Diode" 6-0805_M 4521.07,6933.02 r270 top (schematic designator D1)
D1_4_3 "Diode" 6-0805_M 5261.07,6933.02 r270 top (schematic designator D1)
D1_4_4 "Diode" 6-0805_M 6001.07,6933.02 r270 top (schematic designator D1)
D2_1_1 "Diode" 6-0805_M 3891.07,3693.02 r270 top (schematic designator D2)
D2_1_2 "Diode" 6-0805_M 4631.07,3693.02 r270 top (schematic designator D2)
D2_1_3 "Diode" 6-0805_M 5371.07,3693.02 r270 top (schematic designator D2)
D2_1_4 "Diode" 6-0805_M 6111.07,3693.02 r270 top (schematic designator D2)
D2_2_1 "Diode" 6-0805_M 3891.07,4773.02 r270 top (schematic designator D2)
D2_2_2 "Diode" 6-0805_M 4631.07,4773.02 r270 top (schematic designator D2)
D2_2_3 "Diode" 6-0805_M 5371.07,4773.02 r270 top (schematic designator D2)
D2_2_4 "Diode" 6-0805_M 6111.07,4773.02 r270 top (schematic designator D2)
D2_3_1 "Diode" 6-0805_M 3891.07,5853.02 r270 top (schematic designator D2)
D2_3_2 "Diode" 6-0805_M 4631.07,5853.02 r270 top (schematic designator D2)
D2_3_3 "Diode" 6-0805_M 5371.07,5853.02 r270 top (schematic designator D2)
D2_3_4 "Diode" 6-0805_M 6111.07,5853.02 r270 top (schematic designator D2)
D2_4_1 "Diode" 6-0805_M 3891.07,6933.02 r270 top (schematic designator D2)
D2_4_2 "Diode" 6-0805_M 4631.07,6933.02 r270 top (schematic designator D2)
D2_4_3 "Diode" 6-0805_M 5371.07,6933.02 r270 top (schematic designator D2)
D2_4_4 "Diode" 6-0805_M 6111.07,6933.02 r270 top (schematic designator D2)
D041_1_1 "LED2" 0402R 3981.07,3653.02 r270 top (schematic designator D041)
D041_1_2 "LED2" 0402R 4721.07,3653.02 r270 top (schematic designator D041)
D041_1_3 "LED2" 0402R 5461.07,3653.02 r270 top (schematic designator D041)
D041_1_4 "LED2" 0402R 6201.07,3653.02 r270 top (schematic designator D041)
D041_2_1 "LED2" 0402R 3981.07,4733.02 r270 top (schematic designator D041)
D041_2_2 "LED2" 0402R 4721.07,4733.02 r270 top (schematic designator D041)
D041_2_3 "LED2" 0402R 5461.07,4733.02 r270 top (schematic designator D041)
D041_2_4 "LED2" 0402R 6201.07,4733.02 r270 top (schematic designator D041)
D041_3_1 "LED2" 0402R 3981.07,5813.02 r270 top (schematic designator D041)
D041_3_2 "LED2" 0402R 4721.07,5813.02 r270 top (schematic designator D041)
D041_3_3 "LED2" 0402R 5461.07,5813.02 r270 top (schematic designator D041)
D041_3_4 "LED2" 0402R 6201.07,5813.02 r270 top (schematic designator D041)
D041_4_1 "LED2" 0402R 3981.07,6893.02 r270 top (schematic designator D041)
D041_4_2 "LED2" 0402R 4721.07,6893.02 r270 top (schematic designator D041)
D041_4_3 "LED2" 0402R 5461.07,6893.02 r270 top (schematic designator D041)
D041_4_4 "LED2" 0402R 6201.07,6893.02 r270 top (schematic designator D041)
P1_1_1 "Header 2" HDR1X2 3526.07,3625.14 r90 top (schematic designator P1)
P1_1_2 "Header 2" HDR1X2 4266.07,3625.14 r90 top (schematic designator P1)
P1_1_3 "Header 2" HDR1X2 5006.07,3625.14 r90 top (schematic designator P1)
P1_1_4 "Header 2" HDR1X2 5746.07,3625.14 r90 top (schematic designator P1)
P1_2_1 "Header 2" HDR1X2 3526.07,4705.14 r90 top (schematic designator P1)
P1_2_2 "Header 2" HDR1X2 4266.07,4705.14 r90 top (schematic designator P1)
P1_2_3 "Header 2" HDR1X2 5006.07,4705.14 r90 top (schematic designator P1)
P1_2_4 "Header 2" HDR1X2 5746.07,4705.14 r90 top (schematic designator P1)
P1_3_1 "Header 2" HDR1X2 3526.07,5785.14 r90 top (schematic designator P1)
P1_3_2 "Header 2" HDR1X2 4266.07,5785.14 r90 top (schematic designator P1)
P1_3_3 "Header 2" HDR1X2 5006.07,5785.14 r90 top (schematic designator P1)
P1_3_4 "Header 2" HDR1X2 5746.07,5785.14 r90 top (schematic designator P1)
P1_4_1 "Header 2" HDR1X2 3526.07,6865.14 r90 top (schematic designator P1)
P1_4_2 "Header 2" HDR1X2 4266.07,6865.14 r90 top (schematic designator P1)
P1_4_3 "Header 2" HDR1X2 5006.07,6865.14 r90 top (schematic designator P1)
P1_4_4 "Header 2" HDR1X2 5746.07,6865.14 r90 top (schematic designator P1)
P2_1_1 "Header 6" HDR1X6#1 3526.07,3843.02 r0 top locked (schematic designator P2)
P2_1_2 "Header 6" HDR1X6#1 4266.07,3843.02 r0 top locked (schematic designator P2)
P2_1_3 "Header 6" HDR1X6#1 5006.07,3843.02 r0 top locked (schematic designator P2)
P2_1_4 "Header 6" HDR1X6#1 5746.07,3843.02 r0 top locked (schematic designator P2)
P2_2_1 "Header 6" HDR1X6#1 3526.07,4923.02 r0 top locked (schematic designator P2)
P2_2_2 "Header 6" HDR1X6#1 4266.07,4923.02 r0 top locked (schematic designator P2)
P2_2_3 "Header 6" HDR1X6#1 5006.07,4923.02 r0 top locked (schematic designator P2)
P2_2_4 "Header 6" HDR1X6#1 5746.07,4923.02 r0 top locked (schematic designator P2)
P2_3_1 "Header 6" HDR1X6#1 3526.07,6003.02 r0 top locked (schematic designator P2)
P2_3_2 "Header 6" HDR1X6#1 4266.07,6003.02 r0 top locked (schematic designator P2)
P2_3_3 "Header 6" HDR1X6#1 5006.07,6003.02 r0 top locked (schematic designator P2)
P2_3_4 "Header 6" HDR1X6#1 5746.07,6003.02 r0 top locked (schematic designator P2)
P2_4_1 "Header 6" HDR1X6#1 3526.07,7083.02 r0 top locked (schematic designator P2)
P2_4_2 "Header 6" HDR1X6#1 4266.07,7083.02 r0 top locked (schematic designator P2)
P2_4_3 "Header 6" HDR1X6#1 5006.07,7083.02 r0 top locked (schematic designator P2)
P2_4_4 "Header 6" HDR1X6#1 5746.07,7083.02 r0 top locked (schematic designator P2)
P3_1_1 "Header 6" HDR1X6#2 4036.07,3533.02 r270 top locked (schematic designator P3)
P3_1_2 "Header 6" HDR1X6#2 4776.07,3533.02 r270 top locked (schematic designator P3)
P3_1_3 "Header 6" HDR1X6#2 5516.07,3533.02 r270 top locked (schematic designator P3)
P3_1_4 "Header 6" HDR1X6#2 6256.07,3533.02 r270 top locked (schematic designator P3)
P3_2_1 "Header 6" HDR1X6#2 4036.07,4613.02 r270 top locked (schematic designator P3)
P3_2_2 "Header 6" HDR1X6#2 4776.07,4613.02 r270 top locked (schematic designator P3)
P3_2_3 "Header 6" HDR1X6#2 5516.07,4613.02 r270 top locked (schematic designator P3)
P3_2_4 "Header 6" HDR1X6#2 6256.07,4613.02 r270 top locked (schematic designator P3)
P3_3_1 "Header 6" HDR1X6#2 4036.07,5693.02 r270 top locked (schematic designator P3)
P3_3_2 "Header 6" HDR1X6#2 4776.07,5693.02 r270 top locked (schematic designator P3)
P3_3_3 "Header 6" HDR1X6#2 5516.07,5693.02 r270 top locked (schematic designator P3)
P3_3_4 "Header 6" HDR1X6#2 6256.07,5693.02 r270 top locked (schematic designator P3)
P3_4_1 "Header 6" HDR1X6#2 4036.07,6773.02 r270 top locked (schematic designator P3)
P3_4_2 "Header 6" HDR1X6#2 4776.07,6773.02 r270 top locked (schematic designator P3)
P3_4_3 "Header 6" HDR1X6#2 5516.07,6773.02 r270 top locked (schematic designator P3)
P3_4_4 "Header 6" HDR1X6#2 6256.07,6773.02 r270 top locked (schematic designator P3)
P4_1_1 "Header 3" HDR1X3 3876.07,3023.02 r180 top locked (schematic designator P4)
P4_1_2 "Header 3" HDR1X3 4616.07,3023.02 r180 top locked (schematic designator P4)
P4_1_3 "Header 3" HDR1X3 5356.07,3023.02 r180 top locked (schematic designator P4)
P4_1_4 "Header 3" HDR1X3 6096.07,3023.02 r180 top locked (schematic designator P4)
P4_2_1 "Header 3" HDR1X3 3876.07,4103.02 r180 top locked (schematic designator P4)
P4_2_2 "Header 3" HDR1X3 4616.07,4103.02 r180 top locked (schematic designator P4)
P4_2_3 "Header 3" HDR1X3 5356.07,4103.02 r180 top locked (schematic designator P4)
P4_2_4 "Header 3" HDR1X3 6096.07,4103.02 r180 top locked (schematic designator P4)
P4_3_1 "Header 3" HDR1X3 3876.07,5183.02 r180 top locked (schematic designator P4)
P4_3_2 "Header 3" HDR1X3 4616.07,5183.02 r180 top locked (schematic designator P4)
P4_3_3 "Header 3" HDR1X3 5356.07,5183.02 r180 top locked (schematic designator P4)
P4_3_4 "Header 3" HDR1X3 6096.07,5183.02 r180 top locked (schematic designator P4)
P4_4_1 "Header 3" HDR1X3 3876.07,6263.02 r180 top locked (schematic designator P4)
P4_4_2 "Header 3" HDR1X3 4616.07,6263.02 r180 top locked (schematic designator P4)
P4_4_3 "Header 3" HDR1X3 5356.07,6263.02 r180 top locked (schematic designator P4)
P4_4_4 "Header 3" HDR1X3 6096.07,6263.02 r180 top locked (schematic designator P4)
R21_1_1 "Res1" 0402R 3536.07,3403.02 r0 bottom value=10K (schematic designator R21)
R21_1_2 "Res1" 0402R 4276.07,3403.02 r0 bottom value=10K (schematic designator R21)
R21_1_3 "Res1" 0402R 5016.07,3403.02 r0 bottom value=10K (schematic designator R21)
R21_1_4 "Res1" 0402R 5756.07,3403.02 r0 bottom value=10K (schematic designator R21)
R21_2_1 "Res1" 0402R 3536.07,4483.02 r0 bottom value=10K (schematic designator R21)
R21_2_2 "Res1" 0402R 4276.07,4483.02 r0 bottom value=10K (schematic designator R21)
R21_2_3 "Res1" 0402R 5016.07,4483.02 r0 bottom value=10K (schematic designator R21)
R21_2_4 "Res1" 0402R 5756.07,4483.02 r0 bottom value=10K (schematic designator R21)
R21_3_1 "Res1" 0402R 3536.07,5563.02 r0 bottom value=10K (schematic designator R21)
R21_3_2 "Res1" 0402R 4276.07,5563.02 r0 bottom value=10K (schematic designator R21)
R21_3_3 "Res1" 0402R 5016.07,5563.02 r0 bottom value=10K (schematic designator R21)
R21_3_4 "Res1" 0402R 5756.07,5563.02 r0 bottom value=10K (schematic designator R21)
R21_4_1 "Res1" 0402R 3536.07,6643.02 r0 bottom value=10K (schematic designator R21)
R21_4_2 "Res1" 0402R 4276.07,6643.02 r0 bottom value=10K (schematic designator R21)
R21_4_3 "Res1" 0402R 5016.07,6643.02 r0 bottom value=10K (schematic designator R21)
R21_4_4 "Res1" 0402R 5756.07,6643.02 r0 bottom value=10K (schematic designator R21)
R31_1_1 "Res1" 6-0805_M 3871.07,3123.02 r0 bottom value="20m 0.1W" (schematic designator R31)
R31_1_2 "Res1" 6-0805_M 4611.07,3123.02 r0 bottom value="20m 0.1W" (schematic designator R31)
R31_1_3 "Res1" 6-0805_M 5351.07,3123.02 r0 bottom value="20m 0.1W" (schematic designator R31)
R31_1_4 "Res1" 6-0805_M 6091.07,3123.02 r0 bottom value="20m 0.1W" (schematic designator R31)
R31_2_1 "Res1" 6-0805_M 3871.07,4203.02 r0 bottom value="20m 0.1W" (schematic designator R31)
R31_2_2 "Res1" 6-0805_M 4611.07,4203.02 r0 bottom value="20m 0.1W" (schematic designator R31)
R31_2_3 "Res1" 6-0805_M 5351.07,4203.02 r0 bottom value="20m 0.1W" (schematic designator R31)
R31_2_4 "Res1" 6-0805_M 6091.07,4203.02 r0 bottom value="20m 0.1W" (schematic designator R31)
R31_3_1 "Res1" 6-0805_M 3871.07,5283.02 r0 bottom value="20m 0.1W" (schematic designator R31)
R31_3_2 "Res1" 6-0805_M 4611.07,5283.02 r0 bottom value="20m 0.1W" (schematic designator R31)
R31_3_3 "Res1" 6-0805_M 5351.07,5283.02 r0 bottom value="20m 0.1W" (schematic designator R31)
R31_3_4 "Res1" 6-0805_M 6091.07,5283.02 r0 bottom value="20m 0.1W" (schematic designator R31)
R31_4_1 "Res1" 6-0805_M 3871.07,6363.02 r0 bottom value="20m 0.1W" (schematic designator R31)
R31_4_2 "Res1" 6-0805_M 4611.07,6363.02 r0 bottom value="20m 0.1W" (schematic designator R31)
R31_4_3 "Res1" 6-0805_M 5351.07,6363.02 r0 bottom value="20m 0.1W" (schematic designator R31)
R31_4_4 "Res1" 6-0805_M 6091.07,6363.02 r0 bottom value="20m 0.1W" (schematic designator R31)
R32_1_1 "Res1" 6-0805_M 3646.07,3118.02 r180 bottom value="20m 0.1W" (schematic designator R32)
R32_1_2 "Res1" 6-0805_M 4386.07,3118.02 r180 bottom value="20m 0.1W" (schematic designator R32)
R32_1_3 "Res1" 6-0805_M 5126.07,3118.02 r180 bottom value="20m 0.1W" (schematic designator R32)
R32_1_4 "Res1" 6-0805_M 5866.07,3118.02 r180 bottom value="20m 0.1W" (schematic designator R32)
R32_2_1 "Res1" 6-0805_M 3646.07,4198.02 r180 bottom value="20m 0.1W" (schematic designator R32)
R32_2_2 "Res1" 6-0805_M 4386.07,4198.02 r180 bottom value="20m 0.1W" (schematic designator R32)
R32_2_3 "Res1" 6-0805_M 5126.07,4198.02 r180 bottom value="20m 0.1W" (schematic designator R32)
R32_2_4 "Res1" 6-0805_M 5866.07,4198.02 r180 bottom value="20m 0.1W" (schematic designator R32)
R32_3_1 "Res1" 6-0805_M 3646.07,5278.02 r180 bottom value="20m 0.1W" (schematic designator R32)
R32_3_2 "Res1" 6-0805_M 4386.07,5278.02 r180 bottom value="20m 0.1W" (schematic designator R32)
R32_3_3 "Res1" 6-0805_M 5126.07,5278.02 r180 bottom value="20m 0.1W" (schematic designator R32)
R32_3_4 "Res1" 6-0805_M 5866.07,5278.02 r180 bottom value="20m 0.1W" (schematic designator R32)
R32_4_1 "Res1" 6-0805_M 3646.07,6358.02 r180 bottom value="20m 0.1W" (schematic designator R32)
R32_4_2 "Res1" 6-0805_M 4386.07,6358.02 r180 bottom value="20m 0.1W" (schematic designator R32)
R32_4_3 "Res1" 6-0805_M 5126.07,6358.02 r180 bottom value="20m 0.1W" (schematic designator R32)
R32_4_4 "Res1" 6-0805_M 5866.07,6358.02 r180 bottom value="20m 0.1W" (schematic designator R32)
R041_1_1 "Res1" 0402R 4046.07,3653.02 r270 top value=1K (schematic designator R041)
R041_1_2 "Res1" 0402R 4786.07,3653.02 r270 top value=1K (schematic designator R041)
R041_1_3 "Res1" 0402R 5526.07,3653.02 r270 top value=1K (schematic designator R041)
R041_1_4 "Res1" 0402R 6266.07,3653.02 r270 top value=1K (schematic designator R041)
R041_2_1 "Res1" 0402R 4046.07,4733.02 r270 top value=1K (schematic designator R041)
R041_2_2 "Res1" 0402R 4786.07,4733.02 r270 top value=1K (schematic designator R041)
R041_2_3 "Res1" 0402R 5526.07,4733.02 r270 top value=1K (schematic designator R041)
R041_2_4 "Res1" 0402R 6266.07,4733.02 r270 top value=1K (schematic designator R041)
R041_3_1 "Res1" 0402R 4046.07,5813.02 r270 top value=1K (schematic designator R041)
R041_3_2 "Res1" 0402R 4786.07,5813.02 r270 top value=1K (schematic designator R041)
R041_3_3 "Res1" 0402R 5526.07,5813.02 r270 top value=1K (schematic designator R041)
R041_3_4 "Res1" 0402R 6266.07,5813.02 r270 top value=1K (schematic designator R041)
R041_4_1 "Res1" 0402R 4046.07,6893.02 r270 top value=1K (schematic designator R041)
R041_4_2 "Res1" 0402R 4786.07,6893.02 r270 top value=1K (schematic designator R041)
R041_4_3 "Res1" 0402R 5526.07,6893.02 r270 top value=1K (schematic designator R041)
R041_4_4 "Res1" 0402R 6266.07,6893.02 r270 top value=1K (schematic designator R041)
S051_1_1 "SW-PB" MPTCFP2 3531.07,3298.02 r90 top (schematic designator S051)
S051_1_2 "SW-PB" MPTCFP2 4271.07,3298.02 r90 top (schematic designator S051)
S051_1_3 "SW-PB" MPTCFP2 5011.07,3298.02 r90 top (schematic designator S051)
S051_1_4 "SW-PB" MPTCFP2 5751.07,3298.02 r90 top (schematic designator S051)
S051_2_1 "SW-PB" MPTCFP2 3531.07,4378.02 r90 top (schematic designator S051)
S051_2_2 "SW-PB" MPTCFP2 4271.07,4378.02 r90 top (schematic designator S051)
S051_2_3 "SW-PB" MPTCFP2 5011.07,4378.02 r90 top (schematic designator S051)
S051_2_4 "SW-PB" MPTCFP2 5751.07,4378.02 r90 top (schematic designator S051)
S051_3_1 "SW-PB" MPTCFP2 3531.07,5458.02 r90 top (schematic designator S051)
S051_3_2 "SW-PB" MPTCFP2 4271.07,5458.02 r90 top (schematic designator S051)
S051_3_3 "SW-PB" MPTCFP2 5011.07,5458.02 r90 top (schematic designator S051)
S051_3_4 "SW-PB" MPTCFP2 5751.07,5458.02 r90 top (schematic designator S051)
S051_4_1 "SW-PB" MPTCFP2 3531.07,6538.02 r90 top (schematic designator S051)
S051_4_2 "SW-PB" MPTCFP2 4271.07,6538.02 r90 top (schematic designator S051)
S051_4_3 "SW-PB" MPTCFP2 5011.07,6538.02 r90 top (schematic designator S051)
S051_4_4 "SW-PB" MPTCFP2 5751.07,6538.02 r90 top (schematic designator S051)
U1_1_1 "STM32G030F6P6" TSSOP20 3696.07,3513.02 r0 top (schematic designator U1)
U01_1_1 "SPX3819" SOT23-5 3618.66,3638.02 r180 top (schematic designator U01)
U1_1_2 "STM32G030F6P6" TSSOP20 4436.07,3513.02 r0 top (schematic designator U1)
U01_1_2 "SPX3819" SOT23-5 4358.66,3638.02 r180 top (schematic designator U01)
U1_1_3 "STM32G030F6P6" TSSOP20 5176.07,3513.02 r0 top (schematic designator U1)
U01_1_3 "SPX3819" SOT23-5 5098.66,3638.02 r180 top (schematic designator U01)
U1_1_4 "STM32G030F6P6" TSSOP20 5916.07,3513.02 r0 top (schematic designator U1)
U01_1_4 "SPX3819" SOT23-5 5838.66,3638.02 r180 top (schematic designator U01)
U1_2_1 "STM32G030F6P6" TSSOP20 3696.07,4593.02 r0 top (schematic designator U1)
U01_2_1 "SPX3819" SOT23-5 3618.66,4718.02 r180 top (schematic designator U01)
U1_2_2 "STM32G030F6P6" TSSOP20 4436.07,4593.02 r0 top (schematic designator U1)
U01_2_2 "SPX3819" SOT23-5 4358.66,4718.02 r180 top (schematic designator U01)
U1_2_3 "STM32G030F6P6" TSSOP20 5176.07,4593.02 r0 top (schematic designator U1)
U01_2_3 "SPX3819" SOT23-5 5098.66,4718.02 r180 top (schematic designator U01)
U1_2_4 "STM32G030F6P6" TSSOP20 5916.07,4593.02 r0 top (schematic designator U1)
U01_2_4 "SPX3819" SOT23-5 5838.66,4718.02 r180 top (schematic designator U01)
U1_3_1 "STM32G030F6P6" TSSOP20 3696.07,5673.02 r0 top (schematic designator U1)
U01_3_1 "SPX3819" SOT23-5 3618.66,5798.02 r180 top (schematic designator U01)
U1_3_2 "STM32G030F6P6" TSSOP20 4436.07,5673.02 r0 top (schematic designator U1)
U01_3_2 "SPX3819" SOT23-5 4358.66,5798.02 r180 top (schematic designator U01)
U1_3_3 "STM32G030F6P6" TSSOP20 5176.07,5673.02 r0 top (schematic designator U1)
U01_3_3 "SPX3819" SOT23-5 5098.66,5798.02 r180 top (schematic designator U01)
U1_3_4 "STM32G030F6P6" TSSOP20 5916.07,5673.02 r0 top (schematic designator U1)
U01_3_4 "SPX3819" SOT23-5 5838.66,5798.02 r180 top (schematic designator U01)
U1_4_1 "STM32G030F6P6" TSSOP20 3696.07,6753.02 r0 top (schematic designator U1)
U01_4_1 "SPX3819" SOT23-5 3618.66,6878.02 r180 top (schematic designator U01)
U1_4_2 "STM32G030F6P6" TSSOP20 4436.07,6753.02 r0 top (schematic designator U1)
U01_4_2 "SPX3819" SOT23-5 4358.66,6878.02 r180 top (schematic designator U01)
U1_4_3 "STM32G030F6P6" TSSOP20 5176.07,6753.02 r0 top (schematic designator U1)
U01_4_3 "SPX3819" SOT23-5 5098.66,6878.02 r180 top (schematic designator U01)
U1_4_4 "STM32G030F6P6" TSSOP20 5916.07,6753.02 r0 top (schematic designator U1)
U01_4_4 "SPX3819" SOT23-5 5838.66,6878.02 r180 top (schematic designator U01)
U2_1_1 "DRV8313" TSSOP28 3944.61,3217.74 r90 bottom (schematic designator U2)
U02_1_1 "OSC 16Mhz" SMD3225 3561.07,3500.1 r0 top (schematic designator U02)
u02_1_1 "LP3992-15B5F" SOT23-5 3573.47,3158.02 r0 top (schematic designator u02)
U2_1_2 "DRV8313" TSSOP28 4684.61,3217.74 r90 bottom (schematic designator U2)
U02_1_2 "OSC 16Mhz" SMD3225 4301.07,3500.1 r0 top (schematic designator U02)
u02_1_2 "LP3992-15B5F" SOT23-5 4313.47,3158.02 r0 top (schematic designator u02)
U2_1_3 "DRV8313" TSSOP28 5424.61,3217.74 r90 bottom (schematic designator U2)
U02_1_3 "OSC 16Mhz" SMD3225 5041.07,3500.1 r0 top (schematic designator U02)
u02_1_3 "LP3992-15B5F" SOT23-5 5053.47,3158.02 r0 top (schematic designator u02)
U2_1_4 "DRV8313" TSSOP28 6164.61,3217.74 r90 bottom (schematic designator U2)
U02_1_4 "OSC 16Mhz" SMD3225 5781.07,3500.1 r0 top (schematic designator U02)
u02_1_4 "LP3992-15B5F" SOT23-5 5793.47,3158.02 r0 top (schematic designator u02)
U2_2_1 "DRV8313" TSSOP28 3944.61,4297.74 r90 bottom (schematic designator U2)
U02_2_1 "OSC 16Mhz" SMD3225 3561.07,4580.1 r0 top (schematic designator U02)
u02_2_1 "LP3992-15B5F" SOT23-5 3573.47,4238.02 r0 top (schematic designator u02)
U2_2_2 "DRV8313" TSSOP28 4684.61,4297.74 r90 bottom (schematic designator U2)
U02_2_2 "OSC 16Mhz" SMD3225 4301.07,4580.1 r0 top (schematic designator U02)
u02_2_2 "LP3992-15B5F" SOT23-5 4313.47,4238.02 r0 top (schematic designator u02)
U2_2_3 "DRV8313" TSSOP28 5424.61,4297.74 r90 bottom (schematic designator U2)
U02_2_3 "OSC 16Mhz" SMD3225 5041.07,4580.1 r0 top (schematic designator U02)
u02_2_3 "LP3992-15B5F" SOT23-5 5053.47,4238.02 r0 top (schematic designator u02)
U2_2_4 "DRV8313" TSSOP28 6164.61,4297.74 r90 bottom (schematic designator U2)
U02_2_4 "OSC 16Mhz" SMD3225 5781.07,4580.1 r0 top (schematic designator U02)
u02_2_4 "LP3992-15B5F" SOT23-5 5793.47,4238.02 r0 top (schematic designator u02)
U2_3_1 "DRV8313" TSSOP28 3944.61,5377.74 r90 bottom (schematic designator U2)
U02_3_1 "OSC 16Mhz" SMD3225 3561.07,5660.1 r0 top (schematic designator U02)
u02_3_1 "LP3992-15B5F" SOT23-5 3573.47,5318.02 r0 top (schematic designator u02)
U2_3_2 "DRV8313" TSSOP28 4684.61,5377.74 r90 bottom (schematic designator U2)
U02_3_2 "OSC 16Mhz" SMD3225 4301.07,5660.1 r0 top (schematic designator U02)
u02_3_2 "LP3992-15B5F" SOT23-5 4313.47,5318.02 r0 top (schematic designator u02)
U2_3_3 "DRV8313" TSSOP28 5424.61,5377.74 r90 bottom (schematic designator U2)
U02_3_3 "OSC 16Mhz" SMD3225 5041.07,5660.1 r0 top (schematic designator U02)
u02_3_3 "LP3992-15B5F" SOT23-5 5053.47,5318.02 r0 top (schematic designator u02)
U2_3_4 "DRV8313" TSSOP28 6164.61,5377.74 r90 bottom (schematic designator U2)
U02_3_4 "OSC 16Mhz" SMD3225 5781.07,5660.1 r0 top (schematic designator U02)
u02_3_4 "LP3992-15B5F" SOT23-5 5793.47,5318.02 r0 top (schematic designator u02)
U2_4_1 "DRV8313" TSSOP28 3944.61,6457.74 r90 bottom (schematic designator U2)
U02_4_1 "OSC 16Mhz" SMD3225 3561.07,6740.1 r0 top (schematic designator U02)
u02_4_1 "LP3992-15B5F" SOT23-5 3573.47,6398.02 r0 top (schematic designator u02)
U2_4_2 "DRV8313" TSSOP28 4684.61,6457.74 r90 bottom (schematic designator U2)
U02_4_2 "OSC 16Mhz" SMD3225 4301.07,6740.1 r0 top (schematic designator U02)
u02_4_2 "LP3992-15B5F" SOT23-5 4313.47,6398.02 r0 top (schematic designator u02)
U2_4_3 "DRV8313" TSSOP28 5424.61,6457.74 r90 bottom (schematic designator U2)
U02_4_3 "OSC 16Mhz" SMD3225 5041.07,6740.1 r0 top (schematic designator U02)
u02_4_3 "LP3992-15B5F" SOT23-5 5053.47,6398.02 r0 top (schematic designator u02)
U2_4_4 "DRV8313" TSSOP28 6164.61,6457.74 r90 bottom (schematic designator U2)
U02_4_4 "OSC 16Mhz" SMD3225 5781.07,6740.1 r0 top (schematic designator U02)
u02_4_4 "LP3992-15B5F" SOT23-5 5793.47,6398.02 r0 top (schematic designator u02)
U3_1_1 "INA2181A2IDSQR" VSSOP-10pin 3731.07,3198.02 r0 top (schematic designator U3)
U3_1_2 "INA2181A2IDSQR" VSSOP-10pin 4471.07,3198.02 r0 top (schematic designator U3)
U3_1_3 "INA2181A2IDSQR" VSSOP-10pin 5211.07,3198.02 r0 top (schematic designator U3)
U3_1_4 "INA2181A2IDSQR" VSSOP-10pin 5951.07,3198.02 r0 top (schematic designator U3)
U3_2_1 "INA2181A2IDSQR" VSSOP-10pin 3731.07,4278.02 r0 top (schematic designator U3)
U3_2_2 "INA2181A2IDSQR" VSSOP-10pin 4471.07,4278.02 r0 top (schematic designator U3)
U3_2_3 "INA2181A2IDSQR" VSSOP-10pin 5211.07,4278.02 r0 top (schematic designator U3)
U3_2_4 "INA2181A2IDSQR" VSSOP-10pin 5951.07,4278.02 r0 top (schematic designator U3)
U3_3_1 "INA2181A2IDSQR" VSSOP-10pin 3731.07,5358.02 r0 top (schematic designator U3)
U3_3_2 "INA2181A2IDSQR" VSSOP-10pin 4471.07,5358.02 r0 top (schematic designator U3)
U3_3_3 "INA2181A2IDSQR" VSSOP-10pin 5211.07,5358.02 r0 top (schematic designator U3)
U3_3_4 "INA2181A2IDSQR" VSSOP-10pin 5951.07,5358.02 r0 top (schematic designator U3)
U3_4_1 "INA2181A2IDSQR" VSSOP-10pin 3731.07,6438.02 r0 top (schematic designator U3)
U3_4_2 "INA2181A2IDSQR" VSSOP-10pin 4471.07,6438.02 r0 top (schematic designator U3)
U3_4_3 "INA2181A2IDSQR" VSSOP-10pin 5211.07,6438.02 r0 top (schematic designator U3)
U3_4_4 "INA2181A2IDSQR" VSSOP-10pin 5951.07,6438.02 r0 top (schematic designator U3)

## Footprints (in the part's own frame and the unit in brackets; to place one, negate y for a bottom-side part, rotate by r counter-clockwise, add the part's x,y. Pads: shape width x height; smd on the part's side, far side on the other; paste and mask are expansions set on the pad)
6-0805_M [mm] "Chip Resistor, Body 2.0x1.2mm, IPC Low Density"
  rect 1.4x1.5 smd: 1(-1,0) 2(1,0)
  silkscreen extent 0,-0.65 0,0.65, body extent -1.07,-0.7 1.07,0.7, height 0.7
0402R [mil]
  rect 25x20 smd: 1(-25,0) 2(25,0)
  silkscreen extent -45,-20 45,20
connector [mil]
  rect 20x30 smd: 1(-40,0) 2(40,0)
  Top Layer region: 50,15 50,-15 0,-15 15,0 0,15
  Top Layer region: -50,15 -50,-15 -15,-15 0,0 -15,15
  silkscreen extent -55,-25 55,25
HDR1X2 [mm] "Connector; Header; 2 Position"
  rect 1.5x1.5 hole 0.9: 1(0,0)
  round 1.5 hole 0.9: 2(2.54,0)
  silkscreen extent -1.27,-1.27 3.81,1.27
HDR1X3 [mm] "Connector; Header; 3 Position"
  rect 1.5x1.5 hole 0.9: 1(0,0)
  round 1.5 hole 0.9: 2(2.54,0) 3(5.08,0)
  silkscreen extent -1.27,-1.27 6.35,1.27
HDR1X6#1 [mm] "Connector; Header; 6 Position"
  rect 1.5x1.5 hole 0.9: 1(0,0)
  round 1.5 hole 0.9: 2(2.54,0) 3(5.08,0) 4(7.62,0) 5(10.16,0) 6(12.827,0)
  silkscreen extent -1.27,-1.27 13.97,1.27
HDR1X6#2 [mm] "Connector; Header; 6 Position"
  rect 1.5x1.5 hole 0.9: 1(0,0)
  round 1.5 hole 0.9: 2(2.54,0) 3(5.08,0) 4(7.62,0) 5(10.16,0) 6(12.7,0)
  silkscreen extent -1.27,-1.27 13.97,1.27
MPTCFP2 [mm]
  rect 0.9x2 smd: 1(-2.05,0) 2(2.05,0)
SMD3225 [mm]
  rect 1.3x1.2 smd: 1(-1.1,-0.85) 2(1.1,-0.85) 3(1.1,0.85) 4(-1.1,0.85)
SOT23-5 [mm]
  rect 0.5x1 smd: 1(0,0) 2(-0.95,0) 3(-1.9,0) 4(-1.9,-2.4) 5(0,-2.4)
  silkscreen extent -2.45,-2 0.55,-0.4
TSSOP20 [mm]
  rect 1.5x0.4 smd: 1(0,0)
  oval 1.5x0.4 smd: 2(0,-0.65) 3(0,-1.3) 4(0,-1.95) 5(0,-2.6) 6(0,-3.25) 7(0,-3.9) 8(0,-4.55) 9(0,-5.2) 10(0,-5.85) 11(5.9,-5.85) 12(5.9,-5.2) 13(5.9,-4.55) 14(5.9,-3.9) 15(5.9,-3.25) 16(5.9,-2.6) 17(5.9,-1.95) 18(5.9,-1.3) 19(5.9,-0.65) 20(5.9,0)
  silkscreen extent 1.48,-6.18 4.42,0.33
TSSOP28 [mm]
  rect 1.5x0.4 smd: 1(0,0)
  oval 1.5x0.4 smd: 2(0,-0.65) 3(0,-1.3) 4(0,-1.95) 5(0,-2.6) 6(0,-3.25) 7(0,-3.9) 8(0,-4.55) 9(0,-5.2) 10(0,-5.85) 11(0,-6.5) 12(0,-7.15) 13(0,-7.8) 14(0,-8.45) 15(5.9,-8.45) 16(5.9,-7.8) 17(5.9,-7.15) 18(5.9,-6.5) 19(5.9,-5.85) 20(5.9,-5.2) 21(5.9,-4.55) 22(5.9,-3.9) 23(5.9,-3.25) 24(5.9,-2.6) 25(5.9,-1.95) 26(5.9,-1.3) 27(5.9,-0.65) 28(5.9,0)
  silkscreen extent 1.48,-8.78 4.42,0.33
VSSOP-10pin [mm]
  rrect50% 1.45x0.3 smd: 1(-2.2,1) 2(-2.2,0.5) 3(-2.2,0) 4(-2.2,-0.5) 5(-2.2,-1) 6(2.2,-1) 7(2.2,-0.5) 8(2.2,0) 9(2.2,0.5) 10(2.2,1)
XT_100UF_25V [mm]
  rect 3.5x1.8 smd: 1(-2.7,0) 2(2.7,0)
  silkscreen extent -3.3,-3.3 3.3,3.3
